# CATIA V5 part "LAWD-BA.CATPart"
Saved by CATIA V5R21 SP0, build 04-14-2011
Part number: LAWD-BA.SLDPRT
Bounding box of the stored display mesh (mm): x -1.85 to 1.85, y -1.75 to 1.75, z -0.25 to 0.5
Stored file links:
  C:\Users\user\Desktop\CATIA文件\0-最新文件\LAWD-BA-OK\LAWD-BA.CATPart
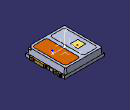
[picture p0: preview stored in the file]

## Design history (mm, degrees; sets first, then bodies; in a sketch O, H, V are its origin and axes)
AxisSystem1: origin (0, 0, 0.5), X (1, 0, 0), Y (0, 1, 0), Z (0, 0, 1)
Set1
  DatumSurface1 to DatumSurface36
  Line1 to Line10: stored without definition
  Circle1: stored without definition
  Circle2: stored without definition
  Line11 to Line17: stored without definition
  Circle3: stored without definition
  Circle4: stored without definition
  Line18: stored without definition
  Line19: stored without definition
  Circle5: stored without definition
  Circle6: stored without definition
  Line20 to Line23: stored without definition
  Circle7: stored without definition
  Circle8: stored without definition
  Line24: stored without definition
  Circle9: stored without definition
  Line25 to Line28: stored without definition
  Circle10: stored without definition
  Line29: stored without definition
  Circle11: stored without definition
  Circle12: stored without definition
  Line30: stored without definition
  Circle13: stored without definition
  Circle14: stored without definition
  Line31: stored without definition
  Circle15: stored without definition
  Circle16: stored without definition
  Line32 to Line37: stored without definition
  Circle17: stored without definition
  Circle18: stored without definition
  Line38: stored without definition
  Circle19: stored without definition
  Line39: stored without definition
  Line40: stored without definition
  Circle20: stored without definition
  Line41 to Line44: stored without definition
  Circle21: stored without definition
  Line45 to Line60: stored without definition
  Circle22: stored without definition
  Line61: stored without definition
  Circle23: stored without definition
  Line62 to Line64: stored without definition
  Circle24: stored without definition
  Line65: stored without definition
  Line66: stored without definition
  Circle25: stored without definition
  Line67 to Line69: stored without definition
  Circle26: stored without definition
  Circle27: stored without definition
  Line70 to Line72: stored without definition
  Circle28: stored without definition
  Line73: stored without definition
  DatumSurface37 to DatumSurface72
  Line74: stored without definition
  Line75: stored without definition
  Circle29: stored without definition
  Circle30: stored without definition
  Line76: stored without definition
  Line77: stored without definition
  Circle31: stored without definition
  Line78 to Line84: stored without definition
  Circle32: stored without definition
  Circle33: stored without definition
  Line85: stored without definition
  Circle34: stored without definition
  Line86 to Line92: stored without definition
  Circle35: stored without definition
  Line93 to Line97: stored without definition
  Circle36: stored without definition
  Line98: stored without definition
  Line99: stored without definition
  Circle37: stored without definition
  Line100 to Line114: stored without definition
  Circle38 to Circle41: stored without definition
  Line115 to Line118: stored without definition
  Circle42: stored without definition
  Circle43: stored without definition
  Line119: stored without definition
  Line120: stored without definition
  Circle44: stored without definition
  Circle45: stored without definition
  Line121 to Line124: stored without definition
  Circle46: stored without definition
  Circle47: stored without definition
  Line125: stored without definition
  Circle48: stored without definition
  Circle49: stored without definition
  Line126 to Line140: stored without definition
  Circle50: stored without definition
  Circle51: stored without definition
  Line141 to Line144: stored without definition
  Circle52: stored without definition
  Line145: stored without definition
  Line146: stored without definition
  Circle53 to Circle56: stored without definition
  DatumSurface73 to DatumSurface105
  Line147 to Line150: stored without definition
  Circle57: stored without definition
  Line151: stored without definition
  Line152: stored without definition
  Circle58: stored without definition
  Circle59: stored without definition
  Line153: stored without definition
  Line154: stored without definition
  Circle60: stored without definition
  Line155: stored without definition
  Circle61: stored without definition
  Circle62: stored without definition
  Line156 to Line162: stored without definition
  Circle63: stored without definition
  Circle64: stored without definition
  Line163 to Line167: stored without definition
  Circle65: stored without definition
  Line168 to Line176: stored without definition
  Circle66: stored without definition
  Line177: stored without definition
  Line178: stored without definition
  Circle67: stored without definition
  Line179: stored without definition
  Circle68: stored without definition
  Line180: stored without definition
  Line181: stored without definition
  Circle69: stored without definition
  Line182: stored without definition
  Line183: stored without definition
  Circle70: stored without definition
  Line184: stored without definition
  Circle71: stored without definition
  Circle72: stored without definition
  Line185 to Line191: stored without definition
  Circle73: stored without definition
  Line192 to Line197: stored without definition
  Circle74: stored without definition
  Line198 to Line200: stored without definition
  Circle75: stored without definition
  Line201 to Line204: stored without definition
  Circle76: stored without definition
  Line205 to Line218: stored without definition
  DatumSurface106 to DatumSurface138
  Line219 to Line222: stored without definition
  Circle77: stored without definition
  Line223: stored without definition
  Line224: stored without definition
  Circle78: stored without definition
  Circle79: stored without definition
  Line225: stored without definition
  Line226: stored without definition
  Circle80: stored without definition
  Line227: stored without definition
  Circle81: stored without definition
  Circle82: stored without definition
  Line228 to Line234: stored without definition
  Circle83: stored without definition
  Circle84: stored without definition
  Line235 to Line239: stored without definition
  Circle85: stored without definition
  Line240 to Line249: stored without definition
  Circle86: stored without definition
  Line250: stored without definition
  Line251: stored without definition
  Circle87: stored without definition
  Line252: stored without definition
  Circle88: stored without definition
  Line253: stored without definition
  Line254: stored without definition
  Circle89: stored without definition
  Line255: stored without definition
  Line256: stored without definition
  Circle90: stored without definition
  Line257: stored without definition
  Circle91: stored without definition
  Circle92: stored without definition
  Line258 to Line265: stored without definition
  Circle93: stored without definition
  Line266 to Line271: stored without definition
  Circle94: stored without definition
  Line272 to Line274: stored without definition
  Circle95: stored without definition
  Line275 to Line278: stored without definition
  Circle96: stored without definition
  Line279 to Line290: stored without definition
  DatumSurface139 to DatumSurface261
  DatumCurve1
  Line291: stored without definition
  DatumCurve2
  Line292: stored without definition
  DatumCurve3
  Line293: stored without definition
  DatumCurve4
  Line294 to Line297: stored without definition
  Circle97: stored without definition
  Line298 to Line304: stored without definition
  Circle98: stored without definition
  Line305 to Line322: stored without definition
  Circle99: stored without definition
  Line323: stored without definition
  Circle100: stored without definition
  Line324 to Line329: stored without definition
  Circle101: stored without definition
  Line330: stored without definition
  Circle102: stored without definition
  Circle103: stored without definition
  Line331: stored without definition
  Circle104: stored without definition
  Line332 to Line337: stored without definition
  Circle105: stored without definition
  Circle106: stored without definition
  Line338: stored without definition
  Circle107: stored without definition
  Circle108: stored without definition
  Line339 to Line342: stored without definition
  Circle109: stored without definition
  Circle110: stored without definition
  Line343 to Line356: stored without definition
  Circle111: stored without definition
  Line357: stored without definition
  Line358: stored without definition
  Circle112: stored without definition
  Circle113: stored without definition
  Line359: stored without definition
  Line360: stored without definition
  Circle114: stored without definition
  Line361: stored without definition
  Circle115: stored without definition
  Circle116: stored without definition
  Line362 to Line367: stored without definition
  Circle117: stored without definition
  Circle118: stored without definition
  Line368 to Line372: stored without definition
  Circle119: stored without definition
  Line373 to Line380: stored without definition
  Circle120: stored without definition
  Line381 to Line383: stored without definition
  Circle121: stored without definition
  Line384: stored without definition
  Line385: stored without definition
  Circle122: stored without definition
  Line386 to Line398: stored without definition
  Circle123: stored without definition
  Line399: stored without definition
  Line400: stored without definition
  Circle124: stored without definition
  Circle125: stored without definition
  Line401: stored without definition
  Line402: stored without definition
  Circle126: stored without definition
  Line403: stored without definition
  Circle127: stored without definition
  Circle128: stored without definition
  Line404 to Line409: stored without definition
  Circle129: stored without definition
  Circle130: stored without definition
  Line410 to Line414: stored without definition
  Circle131: stored without definition
  Line415 to Line422: stored without definition
  Circle132: stored without definition
  Line423 to Line425: stored without definition
  Circle133: stored without definition
  Line426: stored without definition
  Line427: stored without definition
  Circle134: stored without definition
  Line428 to Line435: stored without definition
  Circle135: stored without definition
  Line436: stored without definition
  Line437: stored without definition
  Circle136: stored without definition
  Circle137: stored without definition
  Line438: stored without definition
  Line439: stored without definition
  Circle138: stored without definition
  Line440 to Line446: stored without definition
  Circle139: stored without definition
  Circle140: stored without definition
  Line447 to Line454: stored without definition
  Circle141: stored without definition
  Line455 to Line459: stored without definition
  Circle142: stored without definition
  Line460: stored without definition
  Line461: stored without definition
  Circle143: stored without definition
  Line462 to Line473: stored without definition
  Circle144: stored without definition
  Circle145: stored without definition
  Line474 to Line477: stored without definition
  Circle146: stored without definition
  Line478 to Line489: stored without definition
  Circle147: stored without definition
  Circle148: stored without definition
  Line490 to Line503: stored without definition
  Circle149: stored without definition
  Circle150: stored without definition
  Line504 to Line516: stored without definition
  Circle151: stored without definition
  Line517: stored without definition
  Circle152: stored without definition
  Line518 to Line528: stored without definition
  Circle153: stored without definition
  Circle154: stored without definition
  Line529 to Line542: stored without definition
  Circle155: stored without definition
  Line543: stored without definition
  Line544: stored without definition
  Circle156: stored without definition
  Line545: stored without definition
  Circle157: stored without definition
  Line546 to Line549: stored without definition
  Circle158: stored without definition
  Line550 to Line555: stored without definition
  Circle159: stored without definition
  Line556 to Line560: stored without definition
  Circle160: stored without definition
  Line561: stored without definition
  DatumCurve5
  Line562: stored without definition
  DatumCurve6
  Line563: stored without definition
  DatumCurve7
  Line564: stored without definition
  DatumCurve8
  DatumCurve9
  Line565: stored without definition
  DatumCurve10
  Line566: stored without definition
  DatumCurve11
  Line567: stored without definition
  DatumCurve12
  Line568: stored without definition
  DatumCurve13
  Line569: stored without definition
  DatumCurve14
  Line570: stored without definition
  DatumCurve15
  Line571: stored without definition
  DatumCurve16
  Line572: stored without definition
  Line573: stored without definition
  DatumCurve17
  Line574: stored without definition
  DatumCurve18
  Line575: stored without definition
  DatumCurve19
  Line576 to Line584: stored without definition
  DatumCurve20
  Point1 "几何中心（测试原点）": type Between, FirstPoint vertex [face of DatumSurface256], SecondPoint vertex [face of DatumSurface256], Ratio 0.5
  Point2 "虚拟坐标（白光）": (-0.8071, 0.2994, -0.0989), relative to Point1, in AxisSystem1
  Point3 "虚拟坐标（白转黄）": (0.787, -0.3572, -0.0703), relative to Point1, in AxisSystem1
Body1 (main body)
